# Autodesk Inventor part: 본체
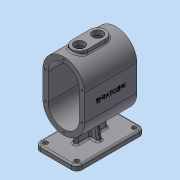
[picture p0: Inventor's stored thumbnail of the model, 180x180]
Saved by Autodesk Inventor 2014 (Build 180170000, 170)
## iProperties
Created: 2016-12
Part Number: 본체
Material: 알루미늄 6061
Document SubType Name: Modeling
Designer: mduedu
Density: 2.71 g/cm^3
Mass: 1171.02 g
Surface Area: 1014.94 cm^2
Volume: 432.112 cm^3
Appearance: 기본값
Author: mduedu
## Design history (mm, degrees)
sketch "스케치1"
  geometry: L1 (40, -25)-(40, 25); L2 (-40, 25)-(-40, -25); L3 (-40, -25)-(40, 25); L4 (40, -25)-(-40, 25); L5 (0, 25)-(0, -25); A1 r 40 centre (0, 25) between (40, 25) and (-40, 25); A2 r 40 centre (0, -25) between (-40, -25) and (40, -25); 1 further point
  constraints: 10 end point, 4 point on circle, 3 tangent, 2 centre point, 2 midpoint, 2 parallel, 1 vertical
  dimensions: "d0" = 130 dimension on A2 A1; "d2" = 80 distance between parallel lines of L1 L2
extrude "돌출1" new body sketch "스케치1" stored distance "d3" = 100; taper "d4" = 0 deg
feature "쉘1" dims "d5" = 10
sketch "스케치2"
  geometry: L1 (-90, 65)-(-100, 65); L2 (-100, 65)-(-100, -65); L3 (-100, -65)-(-90, -65); L4 (-90, -65)-(-90, 65); 2 further points
  constraints: 8 end point, 2 parallel, 1 horizontal, 1 horizontal alignment, 1 midpoint, 1 perpendicular
  dimensions: "d6" = 100 distance from line of L2 point (0, 0); "d7" = 130 distance of L1.end L2.end; "d8" = 10 distance of L2.end L3.end
extrude "돌출2" join sketch "스케치2" stored distance "d9" = 80; taper "d10" = 0 deg
fillet "모깎기1" dims "d11" = 10
sketch "스케치3"
  geometry: L1 (-10, 10)-(-10, 120) reference; L2 (60, 0)-(0, 0) reference; L3 (70, 120)-(70, 10) reference; L4 (0, 130)-(60, 130) reference; A1 r 10 centre (0, 120) between (0, 130) and (-10, 120) reference; A2 r 10 centre (0, 10) between (-10, 10) and (0, 0) reference; A3 r 10 centre (60, 10) between (60, 0) and (70, 10) reference; A4 r 10 centre (60, 120) between (70, 120) and (60, 130) reference; 5 further points
  constraints: 4 coincident
hole "구멍1" sketch "스케치3" at (60, 120), (60, 10), (0, 10), (0, 120) diameter "d12" = 9; stored, may be unused: countersink angle "d16" = 90 deg, drill point angle "d18" = 118 deg; dims "d13" = 6, "d14" = 4, "d15" = 2, "d17" = 8
sketch "스케치5"
  geometry: L1 (34, 35)-(26, 35); L2 (26, 35)-(26, 95); L3 (26, 95)-(34, 95); L4 (34, 95)-(34, 35); L5 (34, 35)-(26, 95); L6 (26, 35)-(34, 95); 1 further point
  constraints: 12 end point, 2 midpoint, 2 parallel, 1 horizontal, 1 perpendicular
  dimensions: "d22" = 8 distance of L2.end L3.end; "d24" = 60 distance of L1.end L2.end
extrude "돌출3" join sketch "스케치5" stored distance "d25" = 80; taper "d26" = 0 deg
feature "면 기울기1" dims angle "d27" = 5 deg
sketch "스케치6"
  geometry: L1 (-30, -90)-(30, -90) reference; L2 (-15.072, -62.052)-(-20, -90); A1 r 40 centre (0, -25) between (-40, -25) and (40, -25) reference; 1 further point
  constraints: 2 end point, 1 point on circle, 1 point on line
  dimensions: "d28" = 20 horizontal distance of A1.centre L2.end; "d29" = 80 deg angle of L2 L1
feature "리브1" sketch "스케치6" dims "d30" = 1, "d31" = 8, "d32" = 0, "d33" = 0, "d34" = 1, "d35" = 1
fillet "모깎기2" dims "d36" = 3
fillet "모깎기3" dims "d37" = 3, "d38" = 3
node "작업 평면1"
sketch "스케치9"
  geometry: 1 further point
sketch "스케치7"
  geometry: L1 (40, 50)-(-40, 50) reference; C1 r 15 at (0, 20); 1 further point
  constraints: 1 centre point, 1 vertical alignment
  dimensions: "d40" = 30 diameter of C1; "d41" = 30 distance from line of C1.centre L1
extrude "돌출4" join sketch "스케치7" stored distance "d42" = 80; taper "d43" = 0 deg
sketch "스케치15"
  geometry: C1 r 15 at (0, -15); C2 r 15 at (0, 20) reference; 1 further point
  constraints: 1 centre point, 1 vertical alignment
  dimensions: "d83" = 30 diameter of C1; "d84" = 35 distance of C1.centre C2.centre
extrude "돌출6" join sketch "스케치15" stored distance "d85" = 10; taper "d86" = 0 deg
hole "구멍2" diameter "d46" = 20; stored, may be unused: countersink angle "d50" = 90 deg, drill point angle "d52" = 118 deg; dims "d44" = 10, "d45" = 10, "d47" = 6, "d48" = 4, "d49" = 2, "d51" = 8
hole "구멍6" diameter "d89" = 20; stored, may be unused: countersink angle "d93" = 90 deg, drill point angle "d95" = 118 deg; dims "d87" = 10, "d88" = 10, "d90" = 6, "d91" = 4, "d92" = 2, "d94" = 8
node "작업 평면2"
sketch "스케치8"
  geometry: C1 r 15 at (0, 0) reference; C2 r 15 at (0, 0); 1 further point
  constraints: 1 centre point, 1 coincident
  dimensions: "d55" = 30 diameter of C2
extrude "돌출5" cut sketch "스케치8" stored distance "d56" = 80; taper "d57" = 0 deg
sketch "스케치16"
  geometry: C1 r 15 at (0, 35); 2 further points
  constraints: 1 centre point, 1 coincident, 1 vertical alignment
  dimensions: "d96" = 30 diameter of C1
extrude "돌출7" cut sketch "스케치16" stored distance "d97" = 10; taper "d98" = 0 deg
sketch "스케치17"
  geometry: L1 (15, 0)-(15, -35); L2 (-15, 0)-(-15, -35); C1 r 10 at (0, 0) reference; C2 r 10 at (0, -35) reference; A1 r 15 centre (0, 0) between (15, 0) and (-15, 0) reference; A2 r 15 centre (0, -35) between (15, -35) and (-15, -35) reference; 1 further point
  constraints: 4 end point, 4 point on circle, 3 tangent, 1 vertical
extrude "돌출8" join sketch "스케치17" stored distance "d99" = 10; taper "d100" = 0 deg
fillet "모깎기5" dims "d101" = 3
chamfer "모따기1" distance "d58" = 1; stored, may be unused: second distance "d59" = 2, angle "d60" = 45 deg
sketch "스케치10"
  geometry: 2 further points
  constraints: 1 coincident, 1 other
feature "엠보싱1" sketch "스케치10" dims "d0" = 130, "d2" = 80, "d11" = 10, "d61" = 0.5, "d62" = 0
sketch "스케치11"
  geometry: 1 further point
hole "구멍3" sketch "스케치11" at (0, 60) diameter "d63" = 3.242; stored, may be unused: countersink angle "d67" = 90 deg, drill point angle "d69" = 120 deg; dims "d64" = 8.6, "d65" = 4, "d66" = 2, "d68" = 10.6
sketch "스케치12"
  geometry: 1 further point
hole "구멍5" sketch "스케치12" at (0, 60) diameter "d70" = 3.242; stored, may be unused: countersink angle "d74" = 90 deg, drill point angle "d76" = 120 deg; dims "d71" = 8.6, "d72" = 4, "d73" = 2, "d75" = 10.6
node "솔리드1"
mirror "대칭1"
pattern_linear "직사각형 패턴1"
pattern_linear "직사각형 패턴2"
node "투영된 루프1"
sketch "스케치13"
  geometry: L1 (-40, 25)-(-40, -25) reference; L2 (40, -25)-(40, 25) reference; L3 (35, 25)-(35, -25); L4 (-35, -25)-(-35, 25); A1 r 40 centre (0, 25) between (40, 25) and (-40, 25) reference; A2 r 40 centre (0, -25) between (-40, -25) and (40, -25) reference; A3 r 35 centre (0, 25) between (35, 25) and (-35, 25); A4 r 35 centre (0, -25) between (-35, -25) and (35, -25); 2 further points
  constraints: 5 point on circle, 4 end point, 2 centre point, 3 other
  dimensions: "d77" = 5 distance between parallel lines of L3 L2
sketch "스케치14"
  geometry: L1 (-40, 25)-(-40, -25) reference; L2 (40, -25)-(40, 25) reference; L3 (35, 25)-(35, -25); L4 (-35, -25)-(-35, 25); A1 r 40 centre (0, 25) between (40, 25) and (-40, 25) reference; A2 r 40 centre (0, -25) between (-40, -25) and (40, -25) reference; A3 r 35 centre (0, 25) between (35, 25) and (-35, 25); A4 r 35 centre (0, -25) between (-35, -25) and (35, -25); 2 further points
  constraints: 5 point on circle, 4 end point, 2 centre point, 3 other
  dimensions: "d80" = 5 distance between parallel lines of L2 L3
node "투영된 루프3"
node "투영된 루프4"
node "투영된 루프5"
